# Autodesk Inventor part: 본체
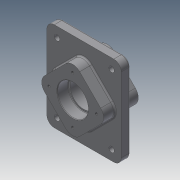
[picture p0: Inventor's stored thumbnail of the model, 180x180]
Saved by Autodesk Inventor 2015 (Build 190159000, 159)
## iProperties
Created: 2026-07
Part Number: 본체
Material: 일반
Document SubType Name: Modeling
Designer: USER
Density: 1 g/cm^3
Appearance: 기본값
Author: USER
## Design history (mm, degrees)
sketch "스케치1"
  geometry: L1 (60, 90)-(-60, 90); L2 (-75, 75)-(-75, -75); L3 (-60, -90)-(60, -90); L4 (75, -75)-(75, 75); L5 (75, 90)-(-75, -90); L6 (-75, 90)-(75, -90); A1 r 15 centre (60, 75) between (75, 75) and (60, 90); A2 r 15 centre (-60, 75) between (-60, 90) and (-75, 75); A3 r 15 centre (-60, -75) between (-75, -75) and (-60, -90); A4 r 15 centre (60, -75) between (60, -90) and (75, -75); 1 further point
  constraints: 12 end point, 8 point on circle, 8 point on line, 8 tangent, 4 centre point, 3 equal radius, 2 midpoint, 2 parallel, 1 horizontal, 1 perpendicular
  dimensions: "d0" = 150 distance of L6.end L5.end; "d1" = 180 distance of L5.end L6.start; "d2" = 15 radius of A1
extrude "돌출1" new body sketch "스케치1" stored distance "d3" = 18; taper "d4" = 0 deg
sketch "스케치3"
  geometry: L1 (-14.142, -56.569)-(-56.569, -14.142); L2 (-56.569, 14.142)-(-14.142, 56.569); L3 (14.142, 56.569)-(56.569, 14.142); L4 (56.569, -14.142)-(14.142, -56.569); A1 r 20 centre (-42.426, 0) between (-56.569, 14.142) and (-56.569, -14.142); A2 r 20 centre (0, 42.426) between (14.142, 56.569) and (-14.142, 56.569); A3 r 20 centre (42.426, 0) between (56.569, -14.142) and (56.569, 14.142); A4 r 20 centre (0, -42.426) between (-14.142, -56.569) and (14.142, -56.569); 6 further points
  constraints: 8 end point, 8 point on circle, 8 point on line, 8 tangent, 4 centre point, 3 equal radius, 1 coincident, 1 vertical alignment, 9 other
  dimensions: "d6" = 100 distance of point (0, 70.711) point (70.711, 0); "d11" = 20 radius of A1
extrude "돌출2" join sketch "스케치3" distance "d7" = 23; taper "d9" = 0 deg; dims "d8" = 47, "d10" = 0
sketch "스케치4"
  geometry: L1 (-60, -90)-(60, -90) reference; L2 (-75, 75)-(-75, -75) reference; C1 r 11 at (-54.5, -70); 1 further point
  constraints: 1 centre point
  dimensions: "d12" = 22 diameter of C1; "d13" = 20 distance from line of L1 C1.centre; "d14" = 20.5 distance from line of C1.centre L2
extrude "돌출3" join sketch "스케치4" distance "d15" = 5; taper "d16" = 0 deg
hole "구멍1" diameter "d19" = 11; stored, may be unused: countersink angle "d23" = 90 deg, drill point angle "d25" = 118 deg; dims "d17" = 10, "d18" = 10, "d20" = 6, "d21" = 4, "d22" = 2, "d24" = 8
sketch "스케치5"
  geometry: C1 r 31 at (0, 0); 1 further point
  constraints: 1 centre point, 1 coincident
  dimensions: "d32" = 62 diameter of C1
extrude "돌출4" cut sketch "스케치5" distance "d33" = 22; taper "d34" = 0 deg
hole "구멍2" diameter "d37" = 54; stored, may be unused: countersink angle "d41" = 90 deg, drill point angle "d43" = 118 deg; dims "d35" = 50, "d36" = 50, "d38" = 6, "d39" = 62, "d40" = 22, "d42" = 8
sketch "스케치6"
  geometry: L1 (0, 0)-(0, 48); C1 r 27 at (0, 0) reference; 1 further point
  constraints: 2 end point, 1 vertical
  dimensions: "d44" = 48 distance of L1.start L1.end
hole "구멍3" sketch "스케치6" at (0, 48) diameter "d45" = 4.917; stored, may be unused: countersink angle "d49" = 90 deg, drill point angle "d51" = 118 deg; dims "d46" = 10, "d47" = 62, "d48" = 22, "d50" = 13
sketch "스케치7"
  geometry: L1 (0, 0)-(0, -48); C1 r 2.458 at (0, -48) reference
  constraints: 2 end point, 1 vertical
  dimensions: "d55" = 48 distance of L1.start L1.end (derived)
hole "구멍4" sketch "스케치7" at (0, -48) diameter "d56" = 4.917; stored, may be unused: countersink angle "d60" = 90 deg, drill point angle "d62" = 118 deg; dims "d57" = 10, "d58" = 62, "d59" = 22, "d61" = 13
sketch "스케치8"
  geometry: L1 (-60, -90)-(60, -90) reference; 3 further points
  constraints: 1 midpoint, 1 vertical alignment, 1 other
  dimensions: "d66" = 15 distance of point (0, -75) point (0, -90)
feature "엠보싱1" sketch "스케치8" dims "d0" = 150, "d1" = 180, "d2" = 15, "d67" = 0.5, "d68" = 0
chamfer "모따기1" distance "d69" = 1; stored, may be unused: second distance "d70" = 2, angle "d71" = 45 deg
fillet "모깎기1" dims "d72" = 1
fillet "모깎기2" dims "d73" = 3
node "솔리드1"
pattern_linear "직사각형 패턴1"
pattern_circular "원형 패턴1" dims angle "d53" = 360 deg
pattern_circular "원형 패턴2" dims angle "d64" = 360 deg
